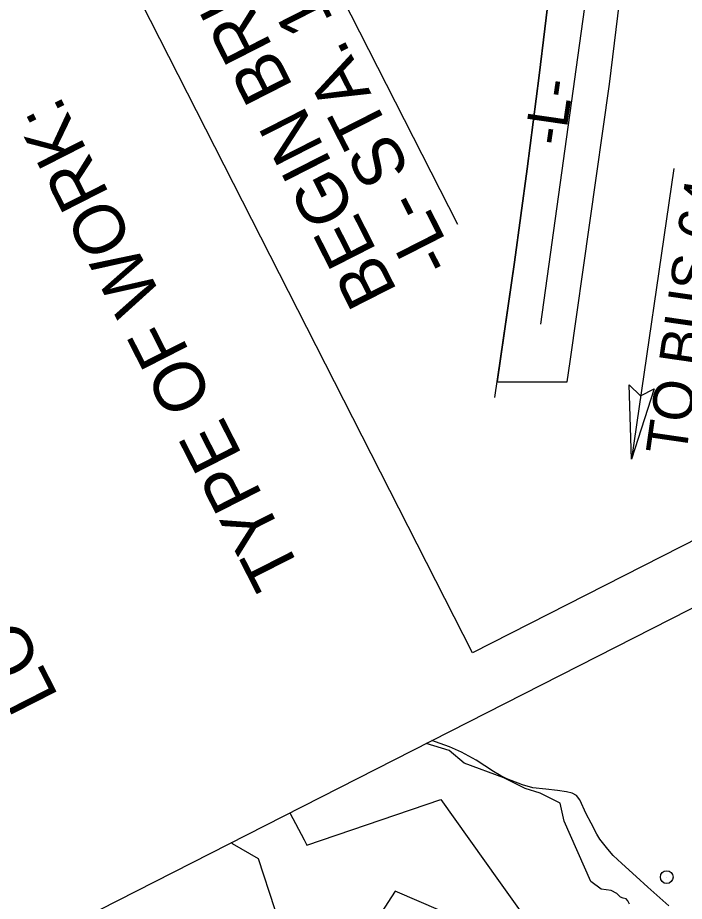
# Model space of a CAD drawing. Extents: x 558484 to 564063, y 513718 to 518374.
# Drawn here: x 559258.8 to 559423.5, y 515102.2 to 515320.6 of the extents above; entities that cross this region are included whole.
import ezdxf

# ---------------------------------------------------------------- set-up
doc = ezdxf.new("R2010")
doc.units = 0
for name, color, linetype in [('Default', 7, 'Continuous'), ('Prop Horizontal Alignment', 7, 'Continuous'), ('Prop Shade Medium', 7, 'Continuous'), ('Prop Terminator CELL', 7, 'Continuous'), ('Sheet Data Field CELL', 7, 'Continuous'), ('Sheet Title CELL', 7, 'Continuous')]:
    doc.layers.add(name, color=color, linetype=linetype)

msp = doc.modelspace()

# ---------------------------------------------------------------- linework, layer by layer
at = {"layer": 'Default'}
for p, q in [((559367.58, 515269.48), (559307.47, 515387.55)), ((559420.9, 515283.36), (559410.46, 515211.5)), ((559419.19, 515108.21), (559419.19, 515108.21)), ((559419.19, 515108.21), (559419.19, 515108.21))]:
    msp.add_line(p, q, dxfattribs=at)
for points in [[(559444.47, 516246.59), (559867.25, 515416.18), (559371.15, 515163.61), (558948.37, 515994.01)], [(559363.74, 514652.18), (559165.18, 515042.19), (559493.11, 515209.15), (559691.68, 514819.14)], [(559363.74, 514652.18), (559165.18, 515042.19), (559493.11, 515209.15), (559691.68, 514819.14)]]:
    msp.add_lwpolyline(points, close=True, dxfattribs=at)
for points in [[(559376.71, 515226.76), (559381.57, 515260.19), (559384.73, 515283.26), (559387.7, 515306.35), (559390.48, 515329.47), (559393.05, 515352.61), (559395.43, 515375.78), (559395.9, 515380.62), (559396.35, 515389.57), (559396.56, 515398.54), (559396.53, 515407.5), (559396.48, 515409.16), (559396.51, 515415.5), (559396.29, 515421.84), (559395.84, 515428.16), (559395.15, 515434.47), (559394.22, 515440.74), (559393.05, 515446.97), (559391.65, 515453.15), (559390.02, 515459.28), (559388.05, 515465.71), (559385.87, 515472.06), (559385.4, 515473.34)], [(559390.6, 515457.11), (559391.65, 515453.15), (559393.05, 515446.97), (559394.22, 515440.74), (559395.15, 515434.47), (559395.84, 515428.16), (559396.29, 515421.84), (559396.51, 515415.5), (559396.48, 515409.16), (559396.53, 515407.5), (559396.56, 515398.54), (559396.35, 515389.57), (559395.9, 515380.62), (559395.43, 515375.78), (559393.05, 515352.61), (559390.48, 515329.47), (559387.7, 515306.35), (559384.73, 515283.26), (559381.57, 515260.19), (559377.27, 515230.63)], [(559394.62, 515230.63), (559395.36, 515235.64), (559405.08, 515304.19), (559411.62, 515358.3)], [(559410, 515101.55), (559409.61, 515102.35), (559409.17, 515102.87), (559408.44, 515103.03), (559407.8, 515103.22), (559406.86, 515104.15), (559405.44, 515104.86), (559403, 515105.19), (559400.4, 515107.16), (559393.87, 515122.06), (559392.88, 515126.46), (559387.92, 515128.95), (559384.22, 515130.13), (559378.91, 515132.74), (559369.14, 515136.34), (559365.44, 515139.53), (559359.74, 515141.25)], [(559419.7, 515101.09), (559414.55, 515105.72), (559411.62, 515108.32), (559408.08, 515111.57), (559405.97, 515113.55), (559404.66, 515115.08), (559402.66, 515117.59), (559401.91, 515118.8), (559400.48, 515121.57), (559399.29, 515123.86), (559397.7, 515127.29), (559396.85, 515128.35), (559395.85, 515128.94), (559394.41, 515129.27), (559392.21, 515129.65), (559389.3, 515129.97), (559386.12, 515130.26), (559383.54, 515131.04), (559379.65, 515132.5), (559378.22, 515133.22), (559376.4, 515134.33), (559372.06, 515137.11), (559368.49, 515139.07), (559365.5, 515140.38), (559362.02, 515141.65), (559361.17, 515141.98)], [(559329.57, 515117.43), (559330.24, 515116.14), (559363.34, 515127.38), (559377.63, 515107.38), (559389.42, 515090.89), (559387.71, 515089.44), (559383.84, 515091.11), (559363.39, 515099.9), (559352.1, 515104.75), (559340.97, 515087.49), (559342.54, 515084.51), (559333.12, 515081.22), (559330.07, 515089.27), (559326.39, 515088), (559318.26, 515112.7), (559311.85, 515116.45), (559311.73, 515116.81)], [(559326.08, 515124.11), (559329.57, 515117.43)]]:
    msp.add_lwpolyline(points, dxfattribs=at)
msp.add_circle((559419.19, 515108.21), 1.58, dxfattribs=at)
at = {"layer": 'Prop Horizontal Alignment'}
msp.add_line((559388.06, 515244.84), (559404.4, 515362.5), dxfattribs=at)
at = {"layer": 'Prop Shade Medium'}
msp.add_line((559377.27, 515230.63), (559394.62, 515230.63), dxfattribs=at)
at = {"layer": 'Prop Terminator CELL'}
msp.add_lwpolyline([(559416.12, 515228.87), (559410.46, 515211.5), (559409.9, 515229.88), (559412.73, 515227.14)], close=True, dxfattribs=at)

# ---------------------------------------------------------------- texts
at = {"layer": 'Default'}
for s, height, rotation, p in [('-L- STA. 12+23.81', 12.5, 116.9819, (559367.32, 515260.46)), ('BEGIN BRIDGE', 12.5, 116.9819, (559352.72, 515253.02)), ('-L-', 10, 81.736, (559393.84, 515288.71)), ('TO BUS 64', 10, 81.736, (559423.89, 515212.11))]:
    msp.add_text(s, height=height, rotation=rotation, dxfattribs=at).set_placement(p)
at = {"layer": 'Sheet Data Field CELL'}
msp.add_text('         CLAY COUNTY         ', height=30, rotation=116.9819, dxfattribs=at).set_placement((559313.61, 514945.44))
at = {"layer": 'Sheet Title CELL'}
for s, height, p in [('TYPE OF WORK:', 12.5001, (559329.16, 515183.48)), ('LOCATION: ', 12.5, (559269, 515152.85))]:
    msp.add_text(s, height=height, rotation=116.9819, dxfattribs=at).set_placement(p)

doc.saveas('drawing.dxf')
